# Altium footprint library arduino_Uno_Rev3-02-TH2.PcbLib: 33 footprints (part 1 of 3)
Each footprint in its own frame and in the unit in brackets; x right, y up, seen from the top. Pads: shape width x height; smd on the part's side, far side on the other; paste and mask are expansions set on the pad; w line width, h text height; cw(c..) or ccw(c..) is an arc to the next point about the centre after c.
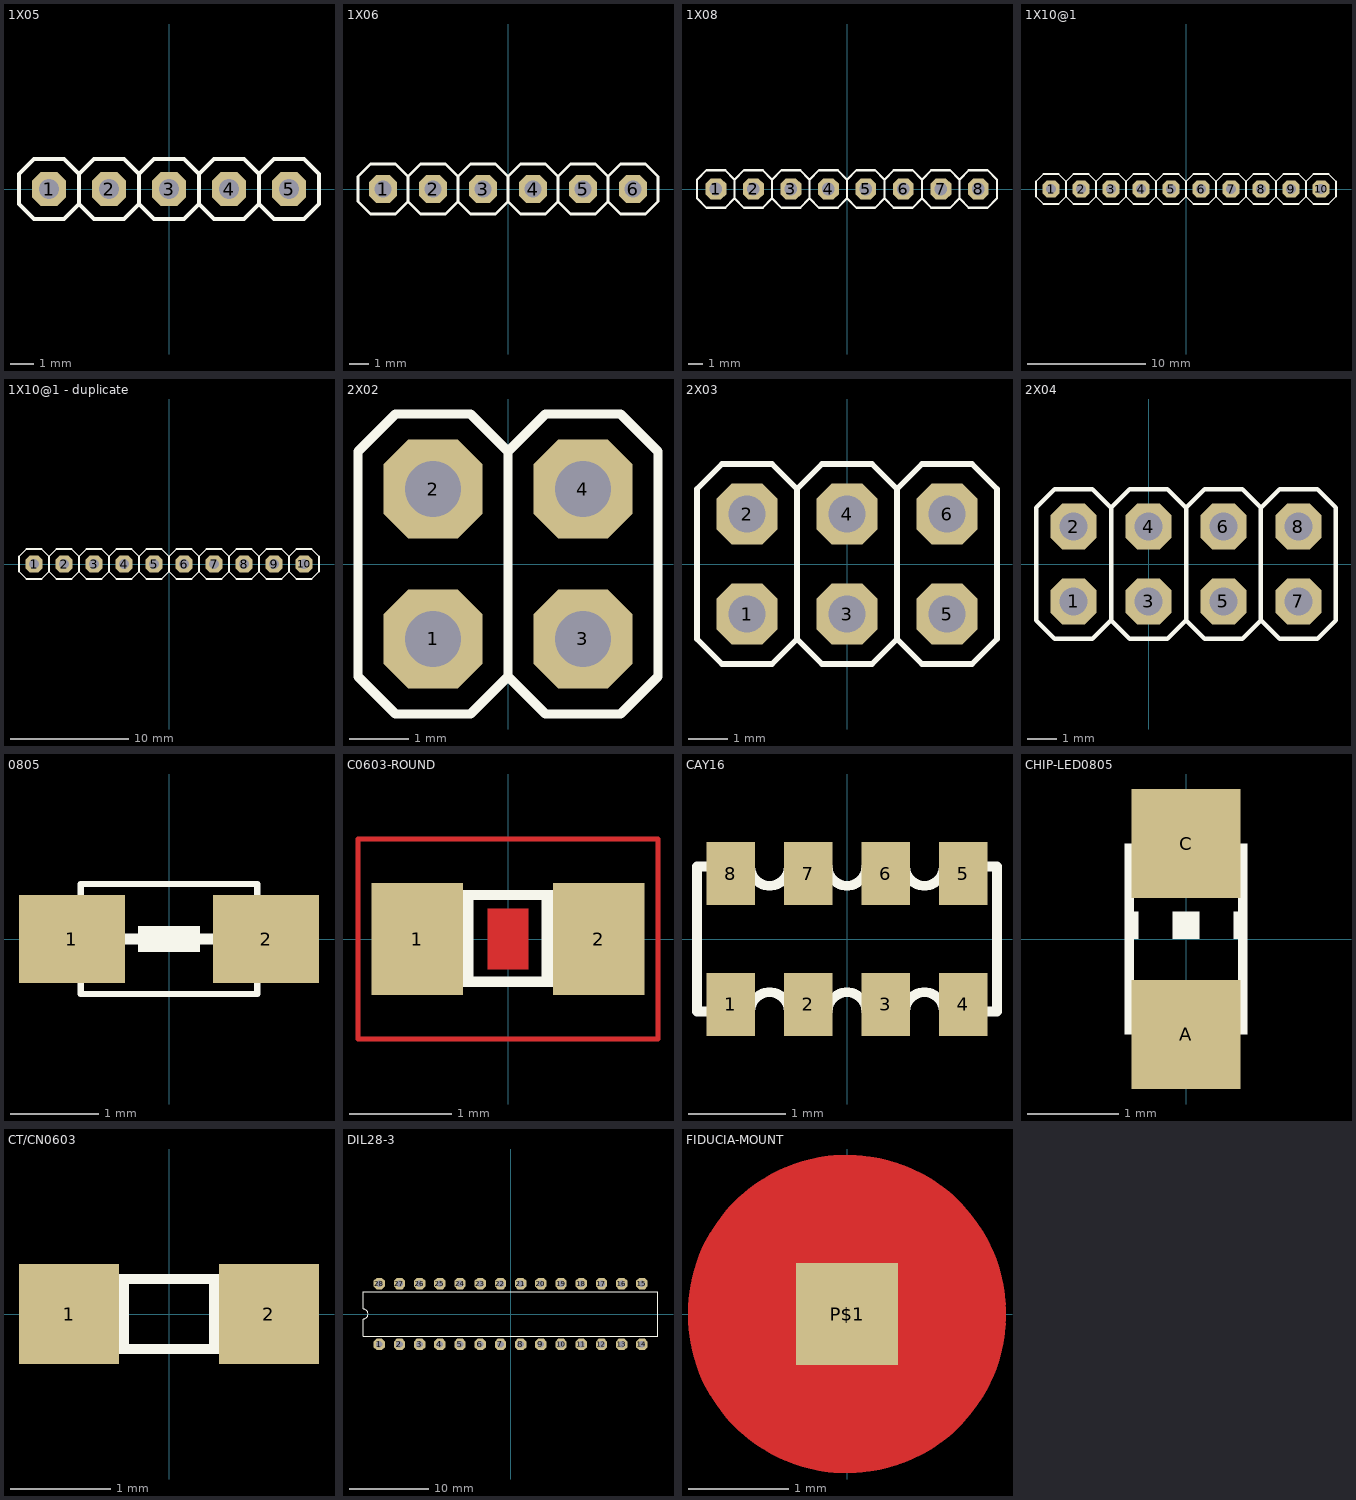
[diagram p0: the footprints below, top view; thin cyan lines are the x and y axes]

## 1X05 [mil]
pads (5):
  oct 56x56 hole 33.46: 1(-200,0) 2(-100,0) 3(0,0) 4(100,0) 5(200,0)
Top Overlay:
  rectangle: -210,-10 -190,10
  rectangle: -110,-10 -90,10
  rectangle: -10,-10 10,10
  rectangle: 90,-10 110,10
  rectangle: 190,-10 210,10
  lines w6: -150,-25 -125,-50 -75,-50 -50,-25 ; -150,-25 -175,-50 -225,-50 -250,-25 -250,25 -225,50 -175,50 -150,25 ; -150,-25 -150,25 ; -150,25 -125,50 -75,50 -50,25 ; -50,-25 -50,25 ; -50,-25 -25,-50 25,-50 50,-25 ; -50,25 -25,50 25,50 50,25 ; 50,-25 75,-50 125,-50 150,-25 ; 50,-25 50,25 ; 50,25 75,50 125,50 150,25 ; 150,-25 175,-50 225,-50 250,-25 250,25 225,50 175,50 150,25 ; 150,-25 150,25

## 1X06 [mil]
pads (6):
  oct 56x56 hole 33.46: 1(-250,0) 2(-150,0) 3(-50,0) 4(50,0) 5(150,0) 6(250,0)
Top Overlay:
  rectangle: 240,-10 260,10
  rectangle: -260,-10 -240,10
  rectangle: -160,-10 -140,10
  rectangle: -60,-10 -40,10
  rectangle: 40,-10 60,10
  rectangle: 140,-10 160,10
  lines w6: -200,-25 -175,-50 -125,-50 -100,-25 ; -200,-25 -225,-50 -275,-50 -300,-25 -300,25 -275,50 -225,50 -200,25 ; -200,-25 -200,25 ; -200,25 -175,50 -125,50 -100,25 ; -100,-25 -100,25 ; -100,-25 -75,-50 -25,-50 0,-25 ; -100,25 -75,50 -25,50 0,25 ; 0,-25 25,-50 75,-50 100,-25 ; 0,-25 0,25 ; 0,25 25,50 75,50 100,25 ; 100,-25 125,-50 175,-50 200,-25 ; 100,-25 100,25 ; 100,25 125,50 175,50 200,25 ; 200,-25 225,-50 275,-50 300,-25 300,25 275,50 225,50 200,25 ; 200,-25 200,25

## 1X08 [mil]
pads (8):
  oct 56x56 hole 33.46: 1(-350,0) 2(-250,0) 3(-150,0) 4(-50,0) 5(50,0) 6(150,0) 7(250,0) 8(350,0)
Top Overlay:
  rectangle: 240,-10 260,10
  rectangle: 140,-10 160,10
  rectangle: 40,-10 60,10
  rectangle: -60,-10 -40,10
  rectangle: -160,-10 -140,10
  rectangle: -260,-10 -240,10
  rectangle: -360,-10 -340,10
  rectangle: 340,-10 360,10
  lines w6: -300,-25 -300,25 ; -300,-25 -325,-50 -375,-50 -400,-25 -400,25 -375,50 -325,50 -300,25 ; -300,-25 -275,-50 -225,-50 -200,-25 ; -300,25 -275,50 -225,50 -200,25 ; -200,-25 -175,-50 -125,-50 -100,-25 ; -200,-25 -200,25 ; -200,25 -175,50 -125,50 -100,25 ; -100,-25 -100,25 ; -100,-25 -75,-50 -25,-50 0,-25 ; -100,25 -75,50 -25,50 0,25 ; 0,-25 0,25 ; 0,-25 25,-50 75,-50 100,-25 ; 0,25 25,50 75,50 100,25 ; 100,-25 125,-50 175,-50 200,-25 ; 100,-25 100,25 ; 100,25 125,50 175,50 200,25 ; 200,-25 200,25 ; 200,-25 225,-50 275,-50 300,-25 ; 200,25 225,50 275,50 300,25 ; 300,-25 300,25 ; 300,-25 325,-50 375,-50 400,-25 400,25 375,50 325,50 300,25

## 1X10@1 [mil]
pads (10):
  oct 56x56 hole 33.46: 1(-450,0) 2(-350,0) 3(-250,0) 4(-150,0) 5(-50,0) 6(50,0) 7(150,0) 8(250,0) 9(350,0) 10(450,0)
Top Overlay:
  rectangle: 340,-10 360,10
  rectangle: 240,-10 260,10
  rectangle: 140,-10 160,10
  rectangle: 40,-10 60,10
  rectangle: -60,-10 -40,10
  rectangle: -160,-10 -140,10
  rectangle: -260,-10 -240,10
  rectangle: -360,-10 -340,10
  rectangle: -460,-10 -440,10
  rectangle: 440,-10 460,10
  lines w6: -400,-25 -400,25 ; -400,-25 -425,-50 -475,-50 -500,-25 -500,25 -475,50 -425,50 -400,25 ; -400,-25 -375,-50 -325,-50 -300,-25 ; -400,25 -375,50 -325,50 -300,25 ; -300,-25 -275,-50 -225,-50 -200,-25 ; -300,-25 -300,25 ; -300,25 -275,50 -225,50 -200,25 ; -200,-25 -200,25 ; -200,-25 -175,-50 -125,-50 -100,-25 ; -200,25 -175,50 -125,50 -100,25 ; -100,-25 -100,25 ; -100,-25 -75,-50 -25,-50 0,-25 ; -100,25 -75,50 -25,50 0,25 ; 0,-25 25,-50 75,-50 100,-25 ; 0,-25 0,25 ; 0,25 25,50 75,50 100,25 ; 100,-25 100,25 ; 100,-25 125,-50 175,-50 200,-25 ; 100,25 125,50 175,50 200,25 ; 200,-25 200,25 ; 200,-25 225,-50 275,-50 300,-25 ; 200,25 225,50 275,50 300,25 ; 300,-25 325,-50 375,-50 400,-25 ; 300,-25 300,25 ; 300,25 325,50 375,50 400,25 ; 400,-25 400,25 ; 400,-25 425,-50 475,-50 500,-25 500,25 475,50 425,50 400,25

## 1X10@1 - duplicate [mil]
pads (10):
  oct 56x56 hole 33.46: 1(-450,0) 2(-350,0) 3(-250,0) 4(-150,0) 5(-50,0) 6(50,0) 7(150,0) 8(250,0) 9(350,0) 10(450,0)
Top Overlay:
  rectangle: 440,-10 460,10
  rectangle: -460,-10 -440,10
  rectangle: -360,-10 -340,10
  rectangle: -260,-10 -240,10
  rectangle: -160,-10 -140,10
  rectangle: -60,-10 -40,10
  rectangle: 40,-10 60,10
  rectangle: 140,-10 160,10
  rectangle: 240,-10 260,10
  rectangle: 340,-10 360,10
  lines w6: -400,-25 -375,-50 -325,-50 -300,-25 ; -400,-25 -425,-50 -475,-50 -500,-25 -500,25 -475,50 -425,50 -400,25 ; -400,-25 -400,25 ; -400,25 -375,50 -325,50 -300,25 ; -300,-25 -300,25 ; -300,-25 -275,-50 -225,-50 -200,-25 ; -300,25 -275,50 -225,50 -200,25 ; -200,-25 -175,-50 -125,-50 -100,-25 ; -200,-25 -200,25 ; -200,25 -175,50 -125,50 -100,25 ; -100,-25 -75,-50 -25,-50 0,-25 ; -100,-25 -100,25 ; -100,25 -75,50 -25,50 0,25 ; 0,-25 0,25 ; 0,-25 25,-50 75,-50 100,-25 ; 0,25 25,50 75,50 100,25 ; 100,-25 125,-50 175,-50 200,-25 ; 100,-25 100,25 ; 100,25 125,50 175,50 200,25 ; 200,-25 225,-50 275,-50 300,-25 ; 200,-25 200,25 ; 200,25 225,50 275,50 300,25 ; 300,-25 300,25 ; 300,-25 325,-50 375,-50 400,-25 ; 300,25 325,50 375,50 400,25 ; 400,-25 425,-50 475,-50 500,-25 500,25 475,50 425,50 400,25 ; 400,-25 400,25

## 2X02 [mil]
pads (4):
  oct 66x66 hole 37.4: 1(-50,-50) 2(-50,50) 3(50,-50) 4(50,50)
Top Overlay:
  rectangle: 40,-60 60,-40
  rectangle: 40,40 60,60
  rectangle: -60,40 -40,60
  rectangle: -60,-60 -40,-40
  lines w6: 0,-75 0,75 ; 0,-75 25,-100 75,-100 100,-75 100,75 75,100 25,100 0,75 ; 0,-75 -25,-100 -75,-100 -100,-75 -100,75 -75,100 -25,100 0,75

## 2X03 [mm]
pads (6):
  oct 1.55x1.55 hole 0.95: 1(-2.54,-1.27) 2(-2.54,1.27) 3(0,-1.27) 4(0,1.27) 5(2.54,-1.27) 6(2.54,1.27)
Top Overlay:
  rectangle: -2.794,-1.524 -2.286,-1.016
  rectangle: -2.794,1.016 -2.286,1.524
  rectangle: -0.254,1.016 0.254,1.524
  rectangle: -0.254,-1.524 0.254,-1.016
  rectangle: 2.286,1.016 2.794,1.524
  rectangle: 2.286,-1.524 2.794,-1.016
  lines w0.152: -1.27,-1.905 -1.905,-2.54 -3.175,-2.54 -3.81,-1.905 -3.81,1.905 -3.175,2.54 -1.905,2.54 -1.27,1.905 ; -1.27,-1.905 -0.635,-2.54 0.635,-2.54 1.27,-1.905 ; -1.27,-1.905 -1.27,1.905 ; -1.27,1.905 -0.635,2.54 0.635,2.54 1.27,1.905 ; 1.27,-1.905 1.27,1.905 ; 1.27,-1.905 1.905,-2.54 3.175,-2.54 3.81,-1.905 3.81,1.905 3.175,2.54 1.905,2.54 1.27,1.905

## 2X04 [mm]
pads (8):
  oct 1.55x1.55 hole 0.95: 1(-2.54,-1.27) 2(-2.54,1.27) 3(0,-1.27) 4(0,1.27) 5(2.54,-1.27) 6(2.54,1.27) 7(5.08,-1.27) 8(5.08,1.27)
Top Overlay:
  rectangle: 4.826,-1.524 5.334,-1.016
  rectangle: 4.826,1.016 5.334,1.524
  rectangle: -2.794,-1.524 -2.286,-1.016
  rectangle: -2.794,1.016 -2.286,1.524
  rectangle: -0.254,1.016 0.254,1.524
  rectangle: -0.254,-1.524 0.254,-1.016
  rectangle: 2.286,1.016 2.794,1.524
  rectangle: 2.286,-1.524 2.794,-1.016
  lines w0.152: -1.27,-1.905 -1.905,-2.54 -3.175,-2.54 -3.81,-1.905 -3.81,1.905 -3.175,2.54 -1.905,2.54 -1.27,1.905 ; -1.27,-1.905 -0.635,-2.54 0.635,-2.54 1.27,-1.905 ; -1.27,-1.905 -1.27,1.905 ; -1.27,1.905 -0.635,2.54 0.635,2.54 1.27,1.905 ; 1.27,-1.905 1.27,1.905 ; 1.27,-1.905 1.905,-2.54 3.175,-2.54 3.81,-1.905 ; 1.27,1.905 1.905,2.54 3.175,2.54 3.81,1.905 ; 3.81,-1.905 4.445,-2.54 5.715,-2.54 6.35,-1.905 6.35,1.905 5.715,2.54 4.445,2.54 3.81,1.905 ; 3.81,-1.905 3.81,1.905

## 0805 [mm]
pads (2):
  rect 1.2x1 smd: 1(-1.1,0) 2(1.1,0)
Top Overlay:
  rectangle: -0.35,-0.15 0.35,0.15
  lines w0.07: -1,-0.625 1,-0.625 1,0.625 -1,0.625 -1,-0.625
  lines w0.127: -1.3,0 1.2,0 ; -1.1,0 1.1,0

## C0603-ROUND [mil]
pads (2):
  rect 35.37x43.31 smd: 1(-35,0) 2(35,0)
Top Layer:
  rectangle: -7.87,-11.81 7.87,11.81
  lines w2: -57.99,-38.7 57.99,-38.7 57.99,38.7 -57.99,38.7 -57.99,-38.7
Top Overlay:
  rectangle: -33,-18.5 -13.31,18.91
  rectangle: 13,-18.5 32.69,18.91
  lines w4: -14.02,-16.5 14.02,-16.5 ; -14.02,17.01 14.02,17.01

## CAY16 [mm]
pads (8):
  rect 0.5x0.65 smd: 1(-1.2,-0.675) 2(-0.4,-0.675) 3(0.4,-0.675) 4(1.2,-0.675) 5(1.2,0.675) 6(0.4,0.675) 7(-0.4,0.675) 8(-1.2,0.675)
Top Overlay:
  lines w0.102: -0.6,-0.75 ccw(c-0.8,-0.75) -1,-0.75 -1.55,-0.75 -1.55,0.75 -1,0.75 ccw(c-0.8,0.75) -0.6,0.75 ; -0.6,-0.75 -0.2,-0.75 cw(c0,-0.75) 0.2,-0.75 0.6,-0.75 ; -0.6,0.75 -0.2,0.75 ccw(c0,0.75) 0.2,0.75 0.6,0.75 ; 0.6,-0.75 cw(c0.8,-0.75) 1,-0.75 1.55,-0.75 1.55,0.75 1,0.75 cw(c0.8,0.75) 0.6,0.75

## CHIP-LED0805 [mm]
pads (2):
  rect 1.2x1.2 smd: A(0,-1.05) C(0,1.05)
Top Overlay:
  rectangle: -0.675,0 -0.525,0.3
  rectangle: 0.525,0 0.675,0.3
  rectangle: -0.15,0 0.15,0.3
  rectangle: -0.675,0.45 0.675,1.05
  rectangle: -0.675,-1.05 0.675,-0.45
  lines w0.102: -0.625,-0.45 -0.625,0.45 ; 0.625,-0.475 0.625,0.45

## CT/CN0603 [mm]
pads (2):
  rect 1x1 smd: 1(-1,0) 2(1,0)
Top Overlay:
  region: 0.75,0.35 0.4,0.35 0.4,-0.35 0.75,-0.35
  rectangle: -0.75,-0.35 -0.4,0.35
  lines w0.102: -0.75,-0.35 -0.75,0.35 0.75,0.35 0.75,-0.35 -0.75,-0.35

## DIL28-3 [mil]
pads (28):
  oct 56x56 hole 33.46: 1(-650,-150) 2(-550,-150) 3(-450,-150) 4(-350,-150) 5(-250,-150) 6(-150,-150) 7(-50,-150) 8(50,-150) 9(150,-150) 10(250,-150) 11(350,-150) 12(450,-150) 13(550,-150) 14(650,-150) 15(650,150) 16(550,150) 17(450,150) 18(350,150) 19(250,150) 20(150,150) 21(50,150) 22(-50,150) 23(-150,150) 24(-250,150) 25(-350,150) 26(-450,150) 27(-550,150) 28(-650,150)
Top Overlay:
  lines w6: -730,-110 -730,-25 ccw(c-730,0) -730,25 -730,110 730,110 730,-110 -730,-110

## DISCLAIMER [mil]

## FIDUCIA-MOUNT [mil]
pads (1):
  rect 40x40 smd: P$1(0,0)
Top Layer:
  circle w86: c0,0 r19.68
  circle w5: c0,0 r59.06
